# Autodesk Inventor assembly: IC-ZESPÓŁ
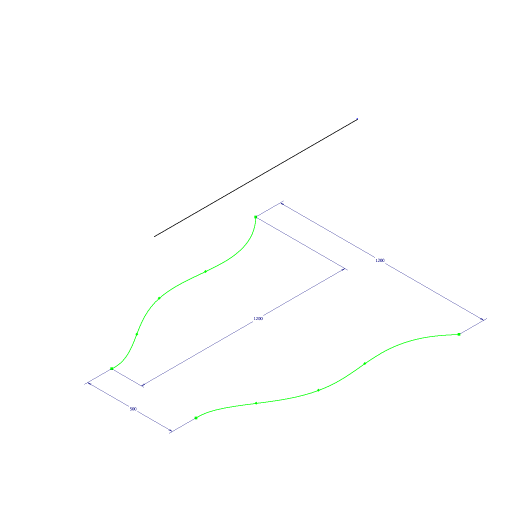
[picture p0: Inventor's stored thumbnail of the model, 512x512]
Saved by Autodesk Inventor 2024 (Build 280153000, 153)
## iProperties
Company: ATC
Created: 2023-03
Part Number: IC-ZESPÓŁ
Document SubType Name: Assembly
Designer: Andrzej Jaskulski
Checked By: A.J.
Engr Approved By: Andrzej Jaskulski
Mfg Approved By: Andrzej Jaskulski
Authority: A.J.
Author: Andrzej Jaskulski
Revision Number: 1/24
Title: A.J.: Kurs R2024-MEP
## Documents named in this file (2)
- C:\Users\AndJas\Documents\R2024-MEP\Obszar roboczy\IC-Zespół docelowy.iam
- C:\Users\AndJas\Documents\R2024-MEP\Obszar roboczy\IC-CZ-Baza z Prowadnicami.ipt
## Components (1 placed, 1 different names)
1. IC-CZ-Baza z Prowadnicami:1
